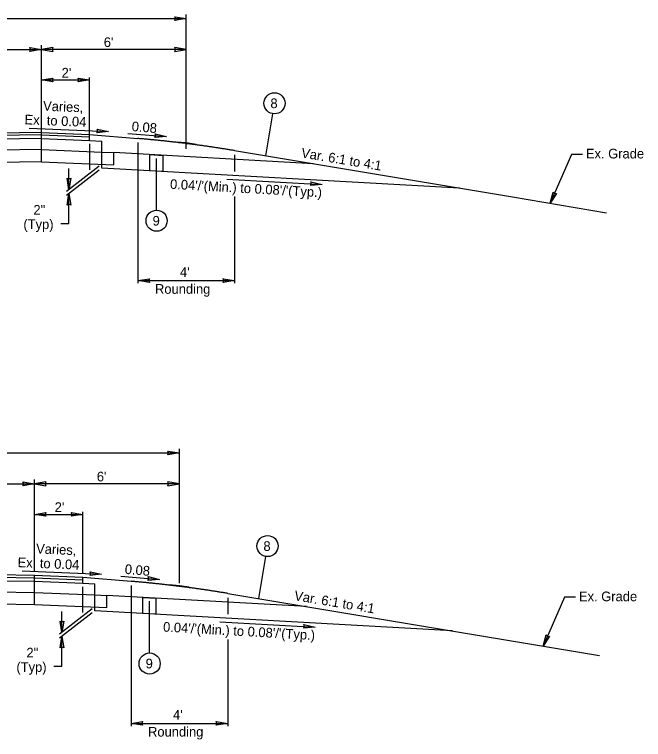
# Model space of a CAD drawing. Extents: x -32 to 684, y -204 to 158.
# Drawn here: x 103.5 to 155.6, y -71.8 to -11.8 of the extents above; entities that cross this region are included whole.
import ezdxf

# ---------------------------------------------------------------- set-up
doc = ezdxf.new("R2010")
doc.units = 0
doc.layers.add('Level 1', color=7, linetype='Continuous')
doc.layers.add('SH_Data', color=7, linetype='Continuous')

msp = doc.modelspace()

# ---------------------------------------------------------------- linework, layer by layer
at = {"layer": 'Level 1'}
for points in [[(117.743, -12.188), (117.747, -12.19)], [(117.745, -12.188), (117.747, -12.19)], [(105.743, -14.743), (105.747, -14.745)], [(105.745, -14.742), (105.747, -14.745)], [(105.755, -14.742), (105.753, -14.745)], [(105.757, -14.743), (105.753, -14.745)], [(117.743, -14.746), (117.747, -14.744)], [(117.745, -14.746), (117.748, -14.744)], [(105.755, -17.268), (105.752, -17.265)], [(105.757, -17.267), (105.753, -17.265)], [(109.743, -17.265), (109.747, -17.266)], [(109.745, -17.264), (109.747, -17.266)], [(111.297, -21.516), (111.3, -21.518)], [(111.298, -21.515), (111.301, -21.518)], [(116.096, -21.945), (116.1, -21.947)], [(116.098, -21.945), (116.101, -21.947)], [(108.035, -26.331), (108.033, -26.334)], [(108.036, -26.332), (108.033, -26.335)], [(128.984, -25.897), (128.988, -25.899)], [(128.986, -25.896), (128.989, -25.899)], [(108.032, -26.664), (108.035, -26.661)], [(108.033, -26.666), (108.035, -26.662)], [(147.868, -27.454), (147.864, -27.456)], [(147.867, -27.456), (147.864, -27.457)], [(113.755, -33.857), (113.753, -33.855)], [(113.757, -33.857), (113.753, -33.855)], [(121.743, -33.854), (121.747, -33.856)], [(121.745, -33.853), (121.747, -33.856)], [(117.167, -48.112), (117.17, -48.114)], [(117.168, -48.112), (117.171, -48.114)], [(105.167, -50.667), (105.17, -50.669)], [(105.168, -50.667), (105.171, -50.669)], [(105.179, -50.667), (105.176, -50.669)], [(105.181, -50.667), (105.177, -50.669)], [(117.167, -50.67), (117.17, -50.668)], [(117.169, -50.67), (117.171, -50.668)], [(105.179, -53.192), (105.176, -53.189)], [(105.181, -53.191), (105.177, -53.189)], [(109.166, -53.189), (109.17, -53.191)], [(109.169, -53.188), (109.171, -53.191)], [(110.72, -58.136), (110.724, -58.138)], [(110.722, -58.136), (110.725, -58.138)], [(115.52, -58.566), (115.524, -58.568)], [(115.522, -58.566), (115.524, -58.568)], [(107.459, -62.951), (107.457, -62.955)], [(107.46, -62.953), (107.457, -62.956)], [(128.408, -62.518), (128.412, -62.52)], [(128.41, -62.517), (128.412, -62.52)], [(107.456, -63.285), (107.458, -63.282)], [(107.456, -63.286), (107.458, -63.283)], [(147.291, -64.074), (147.288, -64.077)], [(147.291, -64.076), (147.288, -64.078)], [(113.179, -70.478), (113.176, -70.476)], [(113.181, -70.477), (113.177, -70.476)], [(121.167, -70.475), (121.17, -70.477)], [(121.169, -70.474), (121.171, -70.477)]]:
    msp.add_lwpolyline(points, dxfattribs=at)
at = {"layer": 'SH_Data'}
for p, q in [((117.75, -22.969), (117.75, -11.849)), ((83.75, -12.189), (117.75, -12.189)), ((116.8, -12.031), (117.75, -12.189)), ((117.75, -12.189), (116.803, -12.348)), ((116.803, -12.348), (116.803, -12.348)), ((105.75, -22.02), (105.75, -14.377)), ((83.75, -14.744), (105.75, -14.744)), ((104.8, -14.586), (105.75, -14.744)), ((105.75, -14.744), (104.803, -14.902)), ((104.803, -14.902), (104.803, -14.902)), ((106.7, -14.586), (105.75, -14.744)), ((117.75, -14.744), (105.75, -14.744)), ((105.75, -14.744), (106.697, -14.902)), ((106.697, -14.902), (106.697, -14.902)), ((116.8, -14.902), (117.75, -14.744)), ((117.75, -14.744), (116.804, -14.586)), ((116.804, -14.586), (116.804, -14.586)), ((105.75, -17.266), (106.696, -17.108)), ((106.7, -17.424), (105.75, -17.266)), ((105.75, -17.266), (109.75, -17.266)), ((106.696, -17.108), (106.696, -17.108)), ((108.8, -17.108), (109.75, -17.266)), ((109.75, -17.266), (108.803, -17.424)), ((109.75, -22.155), (109.75, -17.056)), ((108.803, -17.424), (108.803, -17.424)), ((124.328, -23.537), (124.908, -20.056)), ((104.746, -21.244), (111.304, -21.517)), ((111.304, -21.517), (110.351, -21.636)), ((110.361, -21.32), (111.304, -21.517)), ((105.75, -21.604), (83.75, -21.952)), ((105.75, -21.812), (83.75, -22.161)), ((105.754, -22.104), (83.75, -22.453)), ((105.75, -21.604), (109.75, -21.771)), ((105.75, -24.021), (105.75, -21.604)), ((105.75, -24.052), (105.75, -21.636)), ((105.75, -21.812), (109.75, -21.979)), ((105.754, -22.104), (109.75, -22.271)), ((109.75, -22.271), (109.75, -21.771)), ((109.75, -21.771), (113.75, -22.106)), ((110.351, -21.636), (110.351, -21.636)), ((112.896, -21.679), (116.103, -21.947)), ((116.103, -21.947), (115.147, -22.026)), ((115.147, -22.026), (115.147, -22.026)), ((115.17, -21.71), (116.103, -21.947)), ((109.745, -22.556), (109.745, -24.695)), ((109.75, -22.271), (110.75, -22.312)), ((110.75, -23.229), (110.75, -22.312)), ((113.75, -22.447), (113.75, -34.074)), ((116.917, -22.371), (117.75, -22.441)), ((117.75, -22.441), (118.565, -22.577)), ((105.76, -23.021), (83.75, -23.369)), ((105.76, -23.021), (110.75, -23.229)), ((110.75, -23.229), (111.75, -23.271)), ((110.75, -24.229), (110.75, -23.229)), ((111.75, -24.271), (111.75, -23.271)), ((128.285, -24.197), (111.75, -23.271)), ((121.75, -23.107), (144.76, -26.942)), ((115.289, -28.032), (115.289, -23.755)), ((121.75, -23.464), (121.75, -24.829)), ((149.644, -23.418), (147.864, -27.46)), ((150.544, -23.418), (149.644, -23.418)), ((105.765, -24.021), (83.75, -24.369)), ((105.765, -24.021), (111.75, -24.271)), ((110.537, -24.394), (107.837, -26.491)), ((110.75, -24.55), (110.75, -24.216)), ((140.353, -26.208), (110.75, -24.55)), ((110.524, -24.725), (107.834, -26.814)), ((108.034, -26.338), (108.034, -24.589)), ((108.034, -26.338), (107.876, -25.391)), ((107.876, -25.391), (107.876, -25.391)), ((108.192, -25.388), (108.034, -26.338)), ((121.115, -25.457), (128.991, -25.898)), ((128.054, -25.676), (128.991, -25.898)), ((128.991, -25.898), (128.036, -25.992)), ((128.036, -25.992), (128.036, -25.992)), ((107.876, -27.609), (108.034, -26.659)), ((108.034, -29.131), (108.034, -26.659)), ((108.034, -26.659), (108.192, -27.605)), ((121.75, -26.906), (121.75, -34.074)), ((144.76, -26.942), (152.542, -28.239)), ((147.864, -27.46), (148.104, -26.53)), ((148.394, -26.656), (147.864, -27.46)), ((148.104, -26.53), (148.104, -26.53)), ((108.192, -27.605), (108.192, -27.605)), ((107.375, -29.131), (108.034, -29.131)), ((113.75, -33.855), (114.697, -33.697)), ((114.7, -34.013), (113.75, -33.855)), ((113.75, -33.855), (121.75, -33.855)), ((114.697, -33.697), (114.697, -33.697)), ((120.8, -33.697), (121.75, -33.855)), ((121.75, -33.855), (120.803, -34.013)), ((120.803, -34.013), (120.803, -34.013)), ((116.224, -47.956), (117.174, -48.114)), ((117.174, -58.893), (117.174, -47.773)), ((83.174, -48.114), (117.174, -48.114)), ((117.174, -48.114), (116.227, -48.272)), ((116.227, -48.272), (116.227, -48.272)), ((105.174, -57.944), (105.174, -50.301)), ((83.174, -50.668), (105.174, -50.668)), ((104.224, -50.51), (105.174, -50.668)), ((105.174, -50.668), (104.227, -50.827)), ((104.227, -50.827), (104.227, -50.827)), ((106.124, -50.51), (105.174, -50.668)), ((117.174, -50.668), (105.174, -50.668)), ((105.174, -50.668), (106.12, -50.827)), ((106.12, -50.827), (106.12, -50.827)), ((116.224, -50.827), (117.174, -50.668)), ((117.174, -50.668), (116.227, -50.51)), ((116.227, -50.51), (116.227, -50.51)), ((105.174, -53.19), (106.12, -53.032)), ((106.123, -53.348), (105.174, -53.19)), ((105.174, -53.19), (109.174, -53.19)), ((106.12, -53.032), (106.12, -53.032)), ((108.224, -53.032), (109.174, -53.19)), ((109.174, -53.19), (108.227, -53.348)), ((108.227, -53.348), (108.227, -53.348)), ((109.174, -58.079), (109.174, -52.98)), ((123.751, -60.158), (124.332, -56.676)), ((83.174, -57.877), (105.174, -58.225)), ((83.174, -58.085), (105.174, -58.433)), ((104.169, -57.865), (110.727, -58.138)), ((110.727, -58.138), (109.775, -58.256)), ((109.785, -57.94), (110.727, -58.138)), ((83.174, -58.377), (105.178, -58.725)), ((105.174, -58.225), (109.174, -58.391)), ((105.174, -60.642), (105.174, -58.225)), ((105.174, -60.673), (105.174, -58.257)), ((105.174, -58.433), (109.174, -58.6)), ((105.178, -58.725), (109.174, -58.891)), ((109.174, -58.891), (109.174, -58.391)), ((109.174, -58.391), (113.174, -58.727)), ((109.775, -58.256), (109.775, -58.256)), ((112.32, -58.299), (115.527, -58.568)), ((115.527, -58.568), (114.571, -58.646)), ((114.571, -58.646), (114.571, -58.646)), ((114.594, -58.331), (115.527, -58.568)), ((83.174, -59.293), (105.183, -59.642)), ((109.169, -59.176), (109.169, -61.315)), ((109.174, -58.891), (110.174, -58.933)), ((110.174, -59.85), (110.174, -58.933)), ((113.174, -59.068), (113.174, -70.694)), ((116.34, -58.992), (117.174, -59.062)), ((117.174, -59.062), (117.989, -59.197)), ((105.183, -59.642), (110.174, -59.85)), ((110.174, -59.85), (111.174, -59.891)), ((110.174, -60.85), (110.174, -59.85)), ((111.174, -60.891), (111.174, -59.891)), ((127.709, -60.817), (111.174, -59.891)), ((121.174, -59.728), (144.183, -63.563)), ((83.174, -60.294), (105.188, -60.642)), ((114.713, -64.653), (114.713, -60.376)), ((121.174, -60.085), (121.174, -61.45)), ((149.067, -60.039), (147.287, -64.08)), ((149.968, -60.039), (149.067, -60.039)), ((105.188, -60.642), (111.174, -60.891)), ((109.961, -61.015), (107.26, -63.111)), ((110.174, -61.171), (110.174, -60.837)), ((109.948, -61.346), (107.257, -63.435)), ((107.458, -62.958), (107.458, -61.21)), ((139.776, -62.829), (110.174, -61.171)), ((107.458, -62.958), (107.3, -62.012)), ((107.3, -62.012), (107.3, -62.012)), ((107.616, -62.009), (107.458, -62.958)), ((120.538, -62.078), (128.415, -62.519)), ((127.478, -62.297), (128.415, -62.519)), ((128.415, -62.519), (127.46, -62.612)), ((127.46, -62.612), (127.46, -62.612)), ((107.3, -64.229), (107.458, -63.279)), ((107.458, -65.752), (107.458, -63.279)), ((107.458, -63.279), (107.616, -64.226)), ((121.174, -63.527), (121.174, -70.694)), ((147.287, -64.08), (147.527, -63.151)), ((147.818, -63.277), (147.287, -64.08)), ((147.527, -63.151), (147.527, -63.151)), ((144.183, -63.563), (151.966, -64.86)), ((107.616, -64.226), (107.616, -64.226)), ((106.798, -65.752), (107.458, -65.752)), ((113.174, -70.476), (114.12, -70.318)), ((114.124, -70.634), (113.174, -70.476)), ((113.174, -70.476), (121.174, -70.476)), ((114.12, -70.318), (114.12, -70.318)), ((120.224, -70.318), (121.174, -70.476)), ((121.174, -70.476), (120.227, -70.634)), ((120.227, -70.634), (120.227, -70.634))]:
    msp.add_line(p, q, dxfattribs=at)
for points in [[(114.724, -23.437), (115.813, -23.498), (115.813, -24.834), (114.724, -24.773)], [(114.148, -60.058), (115.237, -60.119), (115.237, -61.454), (114.148, -61.393)]]:
    msp.add_lwpolyline(points, close=True, dxfattribs=at)
for centre in [(125.052, -19.192), (115.289, -28.907), (124.475, -55.813), (114.713, -65.528)]:
    msp.add_circle(centre, 0.875, dxfattribs=at)
for centre, start, end in [((116.561, -12.191), 327.14123, 33.822), ((104.561, -14.746), 327.14123, 33.822), ((106.939, -14.746), 146.178, 212.85877), ((116.561, -14.742), 326.178, 32.85877), ((106.939, -17.264), 147.14123, 213.822), ((108.561, -17.268), 327.14123, 33.822), ((110.116, -21.47), 324.75531, 31.43608), ((114.919, -21.85), 322.35823, 29.03899), ((108.032, -25.149), 237.14123, 303.822), ((127.805, -25.819), 323.22836, 29.90912), ((148.345, -26.373), 213.17538, 279.85615), ((108.036, -27.847), 57.14123, 123.822), ((114.939, -33.853), 147.14123, 213.822), ((120.561, -33.857), 327.14123, 33.822), ((115.985, -48.116), 327.14123, 33.822), ((103.985, -50.671), 327.14123, 33.822), ((106.362, -50.67), 146.178, 212.85877), ((115.985, -50.667), 326.178, 32.85877), ((106.362, -53.188), 147.14123, 213.822), ((107.985, -53.192), 327.14123, 33.822), ((109.539, -58.09), 324.75531, 31.43608), ((114.342, -58.471), 322.35823, 29.03899), ((107.456, -61.77), 237.14123, 303.822), ((127.229, -62.44), 323.22836, 29.90912), ((147.768, -62.993), 213.17538, 279.85615), ((107.46, -64.468), 57.14123, 123.822), ((114.362, -70.474), 147.14123, 213.822), ((119.985, -70.478), 327.14123, 33.822)]:
    msp.add_arc(centre, 0.288, start, end, dxfattribs=at)
for points in [[(121.75, -23.107), (121.596, -23.082), (121.442, -23.057), (121.288, -23.032), (121.135, -23.007), (120.981, -22.982), (120.827, -22.958), (120.673, -22.934), (120.519, -22.91), (120.365, -22.887), (120.212, -22.863), (120.058, -22.84), (119.904, -22.817), (119.75, -22.795), (119.596, -22.772), (119.442, -22.75), (119.288, -22.729), (119.135, -22.707), (118.981, -22.686), (118.827, -22.664), (118.673, -22.644), (118.519, -22.623), (118.365, -22.603), (118.212, -22.583), (118.058, -22.563), (117.904, -22.543), (117.75, -22.524), (117.596, -22.504), (117.442, -22.486), (117.288, -22.467), (117.135, -22.449), (116.981, -22.43), (116.827, -22.412), (116.673, -22.395), (116.519, -22.377), (116.365, -22.36), (116.212, -22.343), (116.058, -22.327), (115.904, -22.31), (115.75, -22.294), (115.596, -22.278), (115.442, -22.262), (115.288, -22.247), (115.135, -22.232), (114.981, -22.217), (114.827, -22.202), (114.673, -22.187), (114.519, -22.173), (114.365, -22.159), (114.212, -22.145), (114.058, -22.132), (113.904, -22.119), (113.75, -22.106)], [(121.174, -59.728), (121.02, -59.703), (120.866, -59.677), (120.712, -59.652), (120.558, -59.628), (120.404, -59.603), (120.251, -59.579), (120.097, -59.555), (119.943, -59.531), (119.789, -59.507), (119.635, -59.484), (119.481, -59.461), (119.328, -59.438), (119.174, -59.416), (119.02, -59.393), (118.866, -59.371), (118.712, -59.349), (118.558, -59.328), (118.404, -59.306), (118.251, -59.285), (118.097, -59.264), (117.943, -59.244), (117.789, -59.223), (117.635, -59.203), (117.481, -59.183), (117.328, -59.164), (117.174, -59.144), (117.02, -59.125), (116.866, -59.106), (116.712, -59.088), (116.558, -59.069), (116.404, -59.051), (116.251, -59.033), (116.097, -59.016), (115.943, -58.998), (115.789, -58.981), (115.635, -58.964), (115.481, -58.947), (115.328, -58.931), (115.174, -58.915), (115.02, -58.899), (114.866, -58.883), (114.712, -58.868), (114.558, -58.852), (114.404, -58.837), (114.251, -58.823), (114.097, -58.808), (113.943, -58.794), (113.789, -58.78), (113.635, -58.766), (113.481, -58.753), (113.328, -58.74), (113.174, -58.727)]]:
    msp.add_spline(points, degree=3, dxfattribs=at)

# ---------------------------------------------------------------- texts
for s, p in [("6'", (110.92, -14.539)), ("2'", (107.43, -17.066)), ('8', (124.712, -19.592)), ('Ex. Grade', (150.827, -23.754)), ('2"', (105.093, -28.406)), ('(Typ)', (104.265, -29.596)), ('9', (114.962, -29.307)), ("4'", (117.225, -33.547)), ('Rounding', (115.159, -34.947)), ("6'", (110.343, -50.463)), ("2'", (106.854, -52.99)), ('8', (124.135, -56.213)), ('Ex. Grade', (150.251, -60.375)), ('2"', (104.517, -65.026)), ('9', (114.386, -65.928)), ('(Typ)', (103.688, -66.217)), ("4'", (116.649, -70.168)), ('Rounding', (114.583, -71.568))]:
    msp.add_text(s, height=0.8, dxfattribs=at).set_placement(p)
for s, rotation, p in [('Varies,', 357.61408, (105.882, -19.8)), ('Ex. to 0.04', 357.61408, (104.347, -20.928)), ('0.08', 355.21699, (113.208, -21.483)), ('Var. 6:1 to 4:1', 350.53768, (127.22, -23.662)), ("0.04'/'(Min.) to 0.08'/'(Typ.)", 356.79433, (116.387, -26.261)), ('Varies,', 357.61408, (105.305, -56.421)), ('Ex. to 0.04', 357.61408, (103.771, -57.549)), ('0.08', 355.21699, (112.632, -58.104)), ('Var. 6:1 to 4:1', 350.53768, (126.643, -60.283)), ("0.04'/'(Min.) to 0.08'/'(Typ.)", 356.79433, (115.81, -62.882))]:
    msp.add_text(s, height=0.8, rotation=rotation, dxfattribs=at).set_placement(p)

doc.saveas('drawing.dxf')
